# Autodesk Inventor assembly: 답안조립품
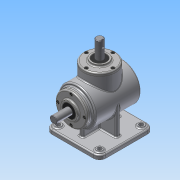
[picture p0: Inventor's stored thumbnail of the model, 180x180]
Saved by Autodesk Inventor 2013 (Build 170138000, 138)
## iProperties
Created: 2015-07
Part Number: 답안조립품
Document SubType Name: Assembly
Designer: Administrator
Author: Administrator
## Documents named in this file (14)
- C:\Users\Administrator\Desktop\450706V1017\답안조립품.iam
- C:\Users\Administrator\Desktop\450706V1017\1.본체.ipt
- C:\Users\Administrator\Desktop\450706V1017\커버.ipt
- C:\Users\Administrator\Desktop\450706V1017\베어링 6203.ipt
- C:\Users\Administrator\Desktop\450706V1017\오일실.ipt
- C:\Users\Administrator\Desktop\450706V1017\M4.ipt
- C:\Users\Administrator\Desktop\450706V1017\메인 축.ipt
- 메인 축.ipt
- C:\Users\Administrator\Desktop\450706V1017\서브 축.ipt
- 서브 축.ipt
- C:\Users\Administrator\Desktop\450706V1017\메인 베벨기어.ipt
- C:\Users\Administrator\Desktop\450706V1017\키 5x5.ipt
- C:\Users\Administrator\Desktop\450706V1017\서브 베벨기어.ipt
- C:\Users\Administrator\Desktop\450706V1017\키 4x4.ipt
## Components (9 placed, 2 different names)
1. 1.본체:1 — 구동, 구동2
2. M4:1
3. M4:2
4. M4:3
5. M4:4
6. M4:5
7. M4:6
8. M4:7
9. M4:8
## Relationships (2: Angle 2)
- 구동 [Angle]: 1.본체:1
- 구동2 [Angle]: 1.본체:1
